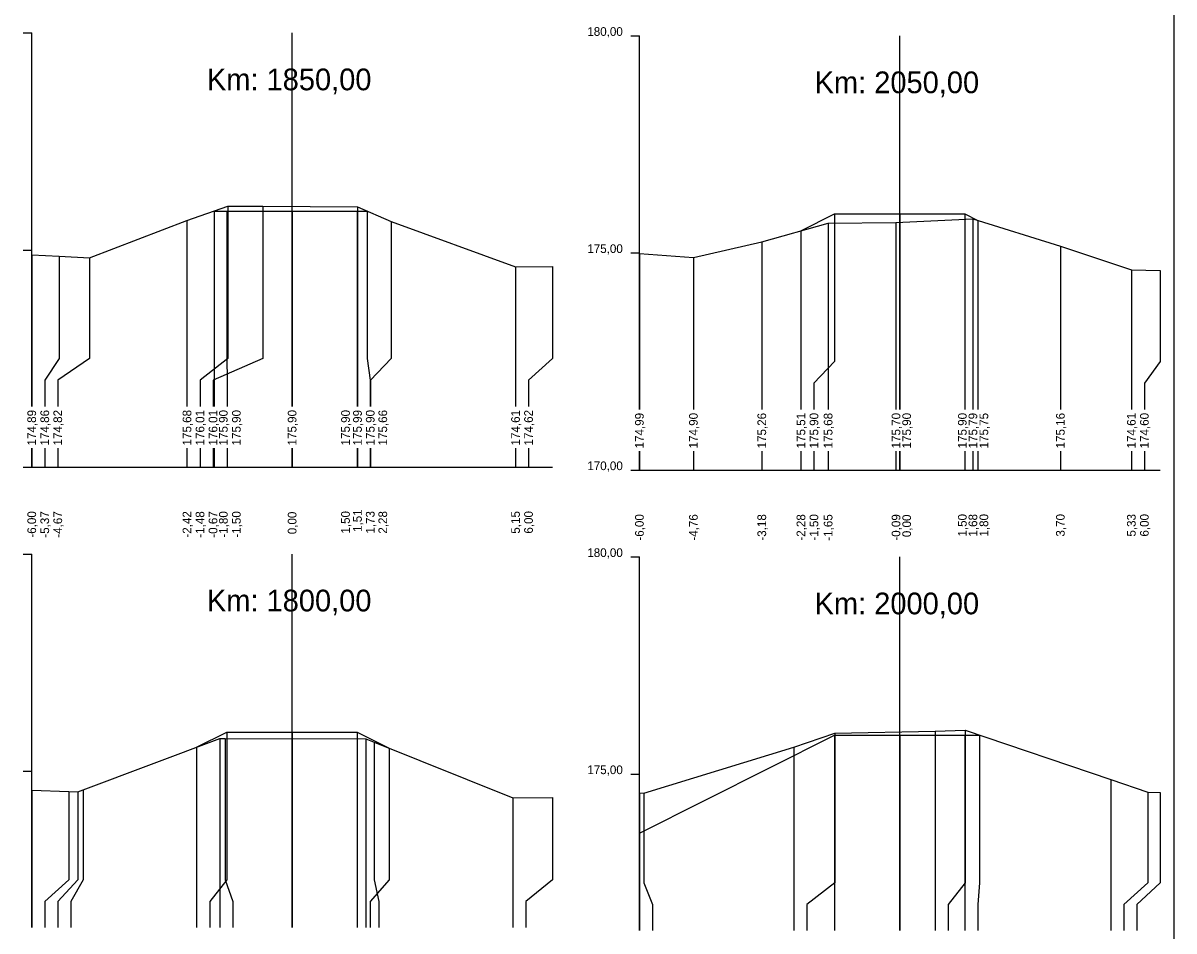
# Model space of a CAD drawing. Extents: x -614174 to -599765, y -1185887 to -1181080.
# Drawn here: x -612592.23 to -612565.71, y -1184221.85 to -1184200.94 of the extents above; entities that cross this region are included whole.
import ezdxf

# ---------------------------------------------------------------- set-up
doc = ezdxf.new("R2010")
doc.units = 0
for name, color, linetype in [('11', 7, 'Continuous'), ('16', 7, 'Continuous'), ('21', 7, 'Continuous'), ('28', 7, 'Continuous'), ('59', 7, 'Continuous'), ('8', 7, 'Continuous'), ('návrh', 7, 'Continuous')]:
    doc.layers.add(name, color=color, linetype=linetype)

msp = doc.modelspace()

# ---------------------------------------------------------------- linework, layer by layer
for points in [[(-612592.029, -1184206.274), (-612591.396, -1184206.307), (-612590.699, -1184206.343), (-612588.452, -1184205.484), (-612587.514, -1184205.157), (-612586.701, -1184205.157), (-612584.524, -1184205.172), (-612583.748, -1184205.506), (-612580.883, -1184206.553), (-612580.029, -1184206.543)], [(-612587.829, -1184205.267), (-612587.53, -1184205.267), (-612586.03, -1184205.267), (-612584.53, -1184205.267), (-612584.303, -1184205.267)], [(-612587.53, -1184205.267), (-612587.53, -1184205.267)], [(-612586.03, -1184205.267), (-612586.03, -1184205.267)], [(-612584.53, -1184205.267), (-612584.53, -1184205.267)], [(-612574.307, -1184205.723), (-612573.53, -1184205.335), (-612572.03, -1184205.335), (-612570.53, -1184205.335), (-612570.232, -1184205.484)], [(-612573.53, -1184205.335), (-612573.53, -1184205.335)], [(-612572.03, -1184205.335), (-612572.03, -1184205.335)], [(-612570.53, -1184205.335), (-612570.53, -1184205.335)], [(-612578.029, -1184206.243), (-612576.785, -1184206.339), (-612575.209, -1184205.974), (-612573.681, -1184205.549), (-612572.117, -1184205.529), (-612570.345, -1184205.449), (-612568.33, -1184206.073), (-612566.695, -1184206.619), (-612566.029, -1184206.636)], [(-612574.306, -1184205.723), (-612574.307, -1184205.723), (-612574.307, -1184205.723)], [(-612588.229, -1184217.617), (-612587.53, -1184217.267), (-612586.03, -1184217.267), (-612584.53, -1184217.267), (-612583.794, -1184217.635)], [(-612587.53, -1184217.267), (-612587.53, -1184217.267)], [(-612586.03, -1184217.267), (-612586.03, -1184217.267)], [(-612584.53, -1184217.267), (-612584.53, -1184217.267)], [(-612578.029, -1184218.667), (-612577.928, -1184218.672), (-612574.47, -1184217.616), (-612573.523, -1184217.288), (-612571.212, -1184217.248), (-612570.524, -1184217.223), (-612567.167, -1184218.357), (-612566.318, -1184218.649), (-612566.029, -1184218.659)], [(-612592.029, -1184218.602), (-612591.172, -1184218.635), (-612590.968, -1184218.644), (-612590.841, -1184218.595), (-612587.695, -1184217.416), (-612587.57, -1184217.417), (-612584.333, -1184217.425), (-612584.142, -1184217.495), (-612580.945, -1184218.779), (-612580.029, -1184218.773)], [(-612578.029, -1184219.592), (-612573.53, -1184217.335), (-612572.03, -1184217.335), (-612570.53, -1184217.335), (-612570.194, -1184217.335)], [(-612573.53, -1184217.335), (-612573.53, -1184217.335)], [(-612572.03, -1184217.335), (-612572.03, -1184217.335)], [(-612570.53, -1184217.335), (-612570.53, -1184217.335)], [(-612588.23, -1184217.617), (-612588.229, -1184217.617), (-612588.229, -1184217.616)]]:
    msp.add_lwpolyline(points)
at = {"layer": '11'}
for points in [[(-612587.514, -1184205.157), (-612587.514, -1184208.666), (-612588.152, -1184209.166), (-612588.152, -1184209.767)], [(-612586.701, -1184205.157), (-612586.701, -1184208.666), (-612587.852, -1184209.166), (-612587.852, -1184209.767)], [(-612587.829, -1184205.267), (-612587.829, -1184208.666), (-612587.829, -1184209.166), (-612587.829, -1184209.767)], [(-612587.53, -1184205.267), (-612587.53, -1184208.666), (-612587.529, -1184209.166), (-612587.529, -1184209.767)], [(-612586.03, -1184205.267), (-612586.03, -1184208.666), (-612586.03, -1184209.166), (-612586.03, -1184209.767)], [(-612584.53, -1184205.267), (-612584.53, -1184208.666), (-612584.53, -1184209.166), (-612584.53, -1184209.767)], [(-612584.524, -1184205.172), (-612584.524, -1184208.666), (-612584.524, -1184209.166), (-612584.524, -1184209.767)], [(-612584.303, -1184205.267), (-612584.303, -1184208.666), (-612584.23, -1184209.166), (-612584.23, -1184209.767)], [(-612573.53, -1184205.335), (-612573.53, -1184208.734), (-612574.007, -1184209.234), (-612574.007, -1184209.835)], [(-612572.03, -1184205.335), (-612572.03, -1184208.734), (-612572.03, -1184209.234), (-612572.03, -1184209.835)], [(-612570.53, -1184205.335), (-612570.53, -1184208.734), (-612570.53, -1184209.234), (-612570.53, -1184209.835)], [(-612588.452, -1184205.484), (-612588.452, -1184208.666), (-612588.452, -1184209.166), (-612588.452, -1184209.767)], [(-612583.748, -1184205.506), (-612583.748, -1184208.666), (-612584.224, -1184209.166), (-612584.224, -1184209.767)], [(-612573.681, -1184205.549), (-612573.681, -1184208.734), (-612573.681, -1184209.234), (-612573.681, -1184209.835)], [(-612572.117, -1184205.529), (-612572.117, -1184208.734), (-612572.117, -1184209.234), (-612572.117, -1184209.835)], [(-612570.345, -1184205.449), (-612570.345, -1184208.734), (-612570.345, -1184209.234), (-612570.345, -1184209.835)], [(-612570.232, -1184205.484), (-612570.232, -1184208.734), (-612570.23, -1184209.234), (-612570.23, -1184209.835)], [(-612574.307, -1184205.723), (-612574.307, -1184208.734), (-612574.307, -1184209.234), (-612574.307, -1184209.835)], [(-612575.209, -1184205.974), (-612575.209, -1184208.734), (-612575.209, -1184209.234), (-612575.209, -1184209.835)], [(-612568.33, -1184206.073), (-612568.33, -1184208.734), (-612568.33, -1184209.234), (-612568.33, -1184209.835)], [(-612592.029, -1184206.274), (-612592.029, -1184208.666), (-612592.029, -1184209.166), (-612592.029, -1184209.767)], [(-612591.396, -1184206.307), (-612591.396, -1184208.666), (-612591.729, -1184209.166), (-612591.729, -1184209.767)], [(-612590.699, -1184206.343), (-612590.699, -1184208.666), (-612591.429, -1184209.166), (-612591.429, -1184209.767)], [(-612578.029, -1184206.243), (-612578.029, -1184208.734), (-612578.029, -1184209.234), (-612578.029, -1184209.835)], [(-612576.785, -1184206.339), (-612576.785, -1184208.734), (-612576.785, -1184209.234), (-612576.785, -1184209.835)], [(-612580.883, -1184206.553), (-612580.883, -1184208.666), (-612580.883, -1184209.166), (-612580.883, -1184209.767)], [(-612580.029, -1184206.543), (-612580.029, -1184208.666), (-612580.583, -1184209.166), (-612580.583, -1184209.767)], [(-612566.695, -1184206.619), (-612566.695, -1184208.734), (-612566.695, -1184209.234), (-612566.695, -1184209.835)], [(-612566.029, -1184206.636), (-612566.029, -1184208.734), (-612566.395, -1184209.234), (-612566.395, -1184209.835)], [(-612592.029, -1184210.726), (-612592.029, -1184211.166)], [(-612591.729, -1184210.726), (-612591.729, -1184211.166)], [(-612591.429, -1184210.726), (-612591.429, -1184211.166)], [(-612588.452, -1184210.726), (-612588.452, -1184211.166)], [(-612588.152, -1184210.726), (-612588.152, -1184211.166)], [(-612587.852, -1184210.726), (-612587.852, -1184211.166)], [(-612587.829, -1184210.726), (-612587.829, -1184211.166)], [(-612587.529, -1184210.726), (-612587.529, -1184211.166)], [(-612586.03, -1184210.726), (-612586.03, -1184211.166)], [(-612584.53, -1184210.726), (-612584.53, -1184211.166)], [(-612584.524, -1184210.726), (-612584.524, -1184211.166)], [(-612584.23, -1184210.726), (-612584.23, -1184211.166)], [(-612584.224, -1184210.726), (-612584.224, -1184211.166)], [(-612580.883, -1184210.726), (-612580.883, -1184211.166)], [(-612580.583, -1184210.726), (-612580.583, -1184211.166)], [(-612578.029, -1184210.794), (-612578.029, -1184211.234)], [(-612576.785, -1184210.794), (-612576.785, -1184211.234)], [(-612575.209, -1184210.794), (-612575.209, -1184211.234)], [(-612574.307, -1184210.794), (-612574.307, -1184211.234)], [(-612574.007, -1184210.794), (-612574.007, -1184211.234)], [(-612573.681, -1184210.794), (-612573.681, -1184211.234)], [(-612572.117, -1184210.794), (-612572.117, -1184211.234)], [(-612572.03, -1184210.794), (-612572.03, -1184211.234)], [(-612570.53, -1184210.794), (-612570.53, -1184211.234)], [(-612570.345, -1184210.794), (-612570.345, -1184211.234)], [(-612570.23, -1184210.794), (-612570.23, -1184211.234)], [(-612568.33, -1184210.794), (-612568.33, -1184211.234)], [(-612566.695, -1184210.794), (-612566.695, -1184211.234)], [(-612566.395, -1184210.794), (-612566.395, -1184211.234)], [(-612587.53, -1184217.267), (-612587.53, -1184220.666), (-612587.929, -1184221.166), (-612587.929, -1184221.767)], [(-612586.03, -1184217.267), (-612586.03, -1184220.666), (-612586.03, -1184221.166), (-612586.03, -1184221.767)], [(-612584.53, -1184217.267), (-612584.53, -1184220.666), (-612584.53, -1184221.166), (-612584.53, -1184221.767)], [(-612571.212, -1184217.248), (-612571.212, -1184220.734), (-612571.212, -1184221.234), (-612571.212, -1184221.835)], [(-612570.524, -1184217.223), (-612570.524, -1184220.734), (-612570.912, -1184221.234), (-612570.912, -1184221.835)], [(-612587.695, -1184217.416), (-612587.695, -1184220.666), (-612587.695, -1184221.166), (-612587.695, -1184221.767)], [(-612587.57, -1184217.417), (-612587.57, -1184220.666), (-612587.395, -1184221.166), (-612587.395, -1184221.767)], [(-612584.333, -1184217.425), (-612584.333, -1184220.666), (-612584.333, -1184221.166), (-612584.333, -1184221.767)], [(-612584.142, -1184217.495), (-612584.142, -1184220.666), (-612584.033, -1184221.166), (-612584.033, -1184221.767)], [(-612573.523, -1184217.288), (-612573.523, -1184220.734), (-612574.17, -1184221.234), (-612574.17, -1184221.835)], [(-612573.53, -1184217.335), (-612573.53, -1184220.734), (-612573.53, -1184221.234), (-612573.53, -1184221.835)], [(-612572.03, -1184217.335), (-612572.03, -1184220.734), (-612572.03, -1184221.234), (-612572.03, -1184221.835)], [(-612570.53, -1184217.335), (-612570.53, -1184220.734), (-612570.53, -1184221.234), (-612570.53, -1184221.835)], [(-612570.194, -1184217.335), (-612570.194, -1184220.734), (-612570.23, -1184221.234), (-612570.23, -1184221.835)], [(-612588.229, -1184217.617), (-612588.229, -1184220.666), (-612588.229, -1184221.166), (-612588.229, -1184221.767)], [(-612583.794, -1184217.635), (-612583.794, -1184220.666), (-612584.23, -1184221.166), (-612584.23, -1184221.767)], [(-612574.47, -1184217.616), (-612574.47, -1184220.734), (-612574.47, -1184221.234), (-612574.47, -1184221.835)], [(-612592.029, -1184218.602), (-612592.029, -1184220.666), (-612592.029, -1184221.166), (-612592.029, -1184221.767)], [(-612590.841, -1184218.595), (-612590.841, -1184220.666), (-612591.129, -1184221.166), (-612591.129, -1184221.767)], [(-612567.167, -1184218.357), (-612567.167, -1184220.734), (-612567.167, -1184221.234), (-612567.167, -1184221.835)], [(-612591.172, -1184218.635), (-612591.172, -1184220.666), (-612591.729, -1184221.166), (-612591.729, -1184221.767)], [(-612590.968, -1184218.644), (-612590.968, -1184220.666), (-612591.429, -1184221.166), (-612591.429, -1184221.767)], [(-612580.945, -1184218.779), (-612580.945, -1184220.666), (-612580.945, -1184221.166), (-612580.945, -1184221.767)], [(-612580.029, -1184218.773), (-612580.029, -1184220.666), (-612580.645, -1184221.166), (-612580.645, -1184221.767)], [(-612578.029, -1184218.667), (-612578.029, -1184220.734), (-612578.029, -1184221.234), (-612578.029, -1184221.835)], [(-612577.928, -1184218.672), (-612577.928, -1184220.734), (-612577.729, -1184221.234), (-612577.729, -1184221.835)], [(-612566.318, -1184218.649), (-612566.318, -1184220.734), (-612566.867, -1184221.234), (-612566.867, -1184221.835)], [(-612566.029, -1184218.659), (-612566.029, -1184220.734), (-612566.567, -1184221.234), (-612566.567, -1184221.835)], [(-612578.029, -1184219.592), (-612578.029, -1184220.734), (-612578.029, -1184221.234), (-612578.029, -1184221.835)]]:
    msp.add_lwpolyline(points, dxfattribs=at)
at = {"layer": '16'}
for p, q in [((-612592.029, -1184211.166), (-612580.029, -1184211.166)), ((-612578.029, -1184211.234), (-612566.029, -1184211.234))]:
    msp.add_line(p, q, dxfattribs=at)
for points in [[(-612584.303, -1184205.267), (-612584.303, -1184205.267), (-612584.303, -1184205.267)], [(-612570.232, -1184205.484), (-612570.232, -1184205.484), (-612570.232, -1184205.484)], [(-612570.194, -1184217.335), (-612570.194, -1184217.335), (-612570.194, -1184217.335)], [(-612583.794, -1184217.635), (-612583.794, -1184217.635), (-612583.795, -1184217.634)]]:
    msp.add_lwpolyline(points, dxfattribs=at)
at = {"layer": '21'}
for p, q in [((-612592.229, -1184201.166), (-612592.029, -1184201.166)), ((-612578.229, -1184201.234), (-612578.029, -1184201.234)), ((-612592.229, -1184206.166), (-612592.029, -1184206.166)), ((-612578.229, -1184206.234), (-612578.029, -1184206.234)), ((-612592.229, -1184211.166), (-612592.029, -1184211.166)), ((-612578.229, -1184211.234), (-612578.029, -1184211.234)), ((-612592.229, -1184213.166), (-612592.029, -1184213.166)), ((-612578.229, -1184213.234), (-612578.029, -1184213.234)), ((-612592.229, -1184218.166), (-612592.029, -1184218.166)), ((-612578.229, -1184218.234), (-612578.029, -1184218.234))]:
    msp.add_line(p, q, dxfattribs=at)
at = {"layer": '28'}
for p, q in [((-612586.029, -1184209.767), (-612586.029, -1184201.166)), ((-612572.029, -1184209.835), (-612572.029, -1184201.234)), ((-612586.029, -1184211.166), (-612586.029, -1184210.726)), ((-612572.029, -1184211.234), (-612572.029, -1184210.794)), ((-612586.029, -1184221.767), (-612586.029, -1184213.166)), ((-612572.029, -1184221.835), (-612572.029, -1184213.234))]:
    msp.add_line(p, q, dxfattribs=at)
at = {"layer": '8'}
for p, q in [((-612592.029, -1184209.767), (-612592.029, -1184201.166)), ((-612578.029, -1184209.835), (-612578.029, -1184201.234)), ((-612592.029, -1184211.166), (-612592.029, -1184210.726)), ((-612578.029, -1184211.234), (-612578.029, -1184210.794)), ((-612592.029, -1184221.767), (-612592.029, -1184213.166)), ((-612578.029, -1184221.835), (-612578.029, -1184213.234))]:
    msp.add_line(p, q, dxfattribs=at)
at = {"layer": 'návrh'}
msp.add_line((-612565.713, -1184186.724), (-612565.713, -1184252.543), dxfattribs=at)

# ---------------------------------------------------------------- texts
msp.add_text('+', height=0.001).set_placement((-612587.829, -1184205.267))
at = {"layer": '16'}
for s, p in [('174,89', (-612591.929, -1184210.666)), ('174,86', (-612591.629, -1184210.666)), ('174,82', (-612591.329, -1184210.666)), ('175,68', (-612588.352, -1184210.666)), ('176,01', (-612588.052, -1184210.666)), ('176,01', (-612587.752, -1184210.666)), ('175,90', (-612587.514, -1184210.666)), ('175,90', (-612587.214, -1184210.666)), ('175,90', (-612585.93, -1184210.666)), ('175,90', (-612584.7, -1184210.666)), ('175,99', (-612584.424, -1184210.666)), ('175,90', (-612584.13, -1184210.666)), ('175,66', (-612583.841, -1184210.666)), ('174,61', (-612580.783, -1184210.666)), ('174,62', (-612580.483, -1184210.666)), ('174,99', (-612577.929, -1184210.734)), ('174,90', (-612576.685, -1184210.734)), ('175,26', (-612575.109, -1184210.734)), ('175,51', (-612574.207, -1184210.734)), ('175,90', (-612573.907, -1184210.734)), ('175,68', (-612573.581, -1184210.734)), ('175,70', (-612572.017, -1184210.734)), ('175,90', (-612571.771, -1184210.734)), ('175,90', (-612570.489, -1184210.734)), ('175,79', (-612570.245, -1184210.734)), ('175,75', (-612569.992, -1184210.734)), ('175,16', (-612568.23, -1184210.734)), ('174,61', (-612566.595, -1184210.734)), ('174,60', (-612566.295, -1184210.734))]:
    msp.add_text(s, height=0.2, rotation=90, dxfattribs=at).set_placement(p)
at = {"layer": '21'}
for s, p in [('180,00', (-612579.229, -1184201.234)), ('175,00', (-612579.229, -1184206.234)), ('170,00', (-612579.229, -1184211.234)), ('180,00', (-612579.229, -1184213.234)), ('175,00', (-612579.229, -1184218.234))]:
    msp.add_text(s, height=0.2, dxfattribs=at).set_placement(p)
at = {"layer": '28'}
for s, p in [('Km: 1850,00', (-612587.993, -1184202.487)), ('Km: 2050,00', (-612573.993, -1184202.554)), ('Km: 1800,00', (-612587.993, -1184214.487)), ('Km: 2000,00', (-612573.993, -1184214.554))]:
    msp.add_text(s, height=0.5, dxfattribs=at).set_placement(p)
at = {"layer": '59'}
for s, p in [('-6,00', (-612591.929, -1184212.789)), ('-5,37', (-612591.629, -1184212.79)), ('-4,67', (-612591.329, -1184212.79)), ('-2,42', (-612588.352, -1184212.788)), ('-1,48', (-612588.052, -1184212.79)), ('-0,67', (-612587.752, -1184212.79)), ('-1,80', (-612587.514, -1184212.789)), ('-1,50', (-612587.214, -1184212.789)), ('0,00', (-612585.93, -1184212.71)), ('1,50', (-612584.7, -1184212.696)), ('1,51', (-612584.424, -1184212.658)), ('1,73', (-612584.13, -1184212.697)), ('2,28', (-612583.841, -1184212.697)), ('5,15', (-612580.783, -1184212.698)), ('6,00', (-612580.483, -1184212.696)), ('-6,00', (-612577.929, -1184212.857)), ('-4,76', (-612576.685, -1184212.858)), ('-3,18', (-612575.109, -1184212.858)), ('-2,28', (-612574.207, -1184212.858)), ('-1,50', (-612573.907, -1184212.857)), ('-1,65', (-612573.581, -1184212.859)), ('-0,09', (-612572.017, -1184212.858)), ('0,00', (-612571.771, -1184212.777)), ('1,50', (-612570.489, -1184212.764)), ('1,68', (-612570.245, -1184212.765)), ('1,80', (-612569.992, -1184212.764)), ('3,70', (-612568.23, -1184212.764)), ('5,33', (-612566.595, -1184212.765)), ('6,00', (-612566.295, -1184212.764))]:
    msp.add_text(s, height=0.2, rotation=90, dxfattribs=at).set_placement(p)

doc.saveas('drawing.dxf')
